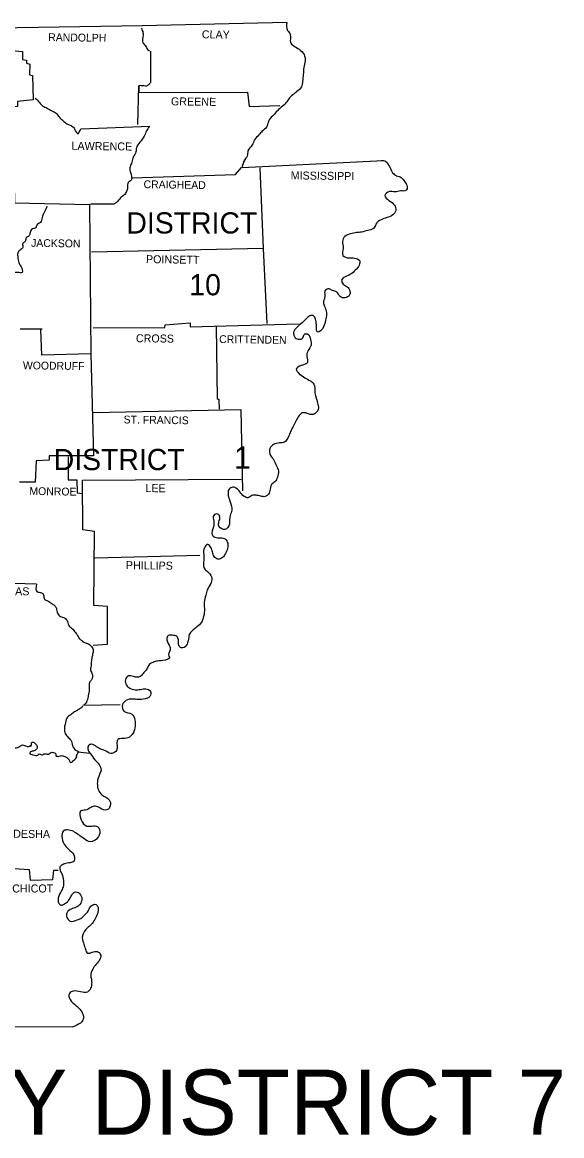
# Model space of a CAD drawing. Extents: x 185 to 5012, y 113 to 2127.
# Drawn here: x 4729 to 5012, y 1376 to 1961 of the extents above; entities that cross this region are included whole.
import ezdxf

# ---------------------------------------------------------------- set-up
doc = ezdxf.new("R2010")
doc.units = 0
for name, color, linetype in [('1', 7, 'Continuous'), ('2', 7, 'Continuous'), ('3', 7, 'Continuous')]:
    doc.layers.add(name, color=color, linetype=linetype)

msp = doc.modelspace()

# ---------------------------------------------------------------- linework, layer by layer
at = {"layer": '1'}
for p, q in [((4844.18, 1884.51), (4845.35, 1888.13)), ((4844.47, 1885.68), (4845.65, 1888.52)), ((4727.55, 1799.78), (4739.2, 1799.78)), ((4760.62, 1601.94), (4780.19, 1602.24))]:
    msp.add_line(p, q, dxfattribs=at)
for points in [[(4330.91, 1956.42), (4489.12, 1956.32), (4627.95, 1956.61), (4791.74, 1959.16), (4867.66, 1960.92)], [(4717.87, 1957.4), (4717.57, 1955.05), (4719.53, 1954.76), (4719.43, 1953.58), (4721.68, 1953.09), (4721.88, 1951.53), (4722.95, 1950.84), (4723.25, 1946.15), (4728.83, 1945.56), (4728.83, 1941.35), (4730.88, 1941.06), (4730.88, 1939.39), (4732.64, 1938.9), (4732.54, 1933.23), (4734.11, 1932.94), (4734.5, 1920.12), (4726.18, 1919.34), (4726.28, 1916.6), (4723.74, 1916.5), (4724.62, 1866.01), (4764.05, 1865.13), (4764.73, 1786.66), (4739, 1785.98), (4738.51, 1799.19)], [(4796.04, 1945.66), (4796.04, 1929.12)], [(4789.39, 1907.11), (4789.88, 1927.56), (4789.88, 1923.94), (4847.11, 1924.23), (4847.9, 1916.6), (4864.04, 1917.18)], [(4759.45, 1904.95), (4795.75, 1906.23)], [(4786.45, 1879.12), (4840.75, 1880.89), (4843.98, 1884.6)], [(4844.18, 1884.51), (4918.44, 1888.32)], [(4853.57, 1884.41), (4855.24, 1842.04), (4857.19, 1802.61)], [(4776.86, 1865.33), (4764.93, 1865.33), (4764.05, 1865.13)], [(4855.24, 1842.04), (4765.12, 1839.99)], [(4765.91, 1800.36), (4803.67, 1800.56), (4803.77, 1801.93), (4816.88, 1802.91), (4816.88, 1800.85), (4873.82, 1802.42)], [(4830.58, 1800.85), (4831.07, 1763.18), (4831.95, 1762.6), (4832.24, 1757.51)], [(4764.73, 1786.66), (4766.2, 1733.05), (4742.91, 1732.95), (4742.82, 1730.8), (4736.07, 1730.41), (4735.48, 1719.25), (4727.26, 1719.25)], [(4765.91, 1755.85), (4843.59, 1757.41)], [(4843.59, 1757.41), (4844.37, 1714.56)], [(4752.89, 1732.46), (4752.8, 1720.33), (4757.3, 1720.33), (4757.49, 1713.58), (4760.33, 1713.28)], [(4765.91, 1633.54), (4773.54, 1634.03), (4773.44, 1653.9), (4766.3, 1654.38), (4766.69, 1693.23), (4760.53, 1694.11), (4760.33, 1720.23), (4843.79, 1720.82)], [(4766.89, 1679.43), (4822.07, 1680.8)], [(4736.26, 1665.64), (4699.28, 1666.61), (4699.08, 1654.58), (4624.23, 1654.29)], [(4733.03, 1580.22), (4733.33, 1580.51), (4733.62, 1580.81), (4733.62, 1580.81)], [(4719.24, 1516.43), (4732.35, 1515.65), (4732.93, 1509.97), (4744.77, 1510.36), (4745.26, 1515.16), (4747.51, 1515.16)], [(4396.46, 1512.61), (4396.66, 1433.46), (4755.24, 1432.87)]]:
    msp.add_lwpolyline(points, dxfattribs=at)
for points in [[(4867.66, 1960.92), (4868.15, 1956.61), (4869.52, 1954.36), (4869.72, 1950.25), (4871.38, 1948.49), (4874.22, 1946.73), (4876.76, 1943.89), (4877.35, 1940.57), (4876.56, 1937.14), (4876.37, 1933.33), (4875.98, 1930), (4875.39, 1926.97), (4873.04, 1924.52), (4870.79, 1922.76), (4868.74, 1920.71), (4867.27, 1918.55), (4864.73, 1916.21), (4862.18, 1913.76), (4860.13, 1911.61), (4858.07, 1908.87), (4857.09, 1905.83), (4854.84, 1903.68), (4853.08, 1901.73), (4850.73, 1899.08), (4849.56, 1896.44), (4847.31, 1893.41), (4846.82, 1890.47), (4845.35, 1888.13), (4845.26, 1887.73)], [(4791.25, 1957.89), (4792.13, 1955.44), (4792.03, 1952.8), (4792.03, 1950.35), (4793.3, 1948.69), (4794.57, 1946.63), (4795.55, 1945.75)], [(4795.65, 1928.83), (4794.38, 1927.56), (4791.93, 1927.56), (4789.88, 1927.56)], [(4735.58, 1921), (4737.73, 1918.75), (4739.59, 1916.89), (4741.74, 1915.81), (4744.28, 1914.35), (4746.53, 1913.17), (4748, 1911.31), (4750.06, 1909.26), (4752.11, 1907.6), (4755.34, 1906.03), (4756.42, 1904.37), (4757.88, 1902.31), (4759.45, 1904.95)], [(4795.45, 1906.13), (4793.99, 1903.78), (4792.81, 1901.04), (4790.46, 1897.91), (4788.7, 1894.88), (4788.41, 1892.82), (4787.04, 1890.08), (4786.26, 1887.34), (4785.38, 1884.99), (4785.38, 1882.55), (4786.06, 1880.1), (4785.87, 1877.85), (4784.4, 1876.78), (4784.01, 1873.94), (4783.42, 1871.98), (4782.15, 1870.03), (4780.29, 1868.56), (4778.33, 1866.31), (4776.86, 1865.33)], [(4917.36, 1888.22), (4918.44, 1888.32), (4921.77, 1884.8), (4923.23, 1881.86), (4925.39, 1880.2), (4927.83, 1879.32), (4929.69, 1877.07), (4930.96, 1874.62), (4930.28, 1872.47), (4927.54, 1872.28), (4924.51, 1871.79), (4921.57, 1871.88), (4919.22, 1869.93), (4921.38, 1867.29), (4924.21, 1864.84), (4925, 1862.2), (4923.43, 1859.65), (4920.3, 1858.28), (4917.27, 1857.11), (4914.53, 1854.76), (4913.25, 1852.51), (4910.22, 1851.53), (4907.09, 1850.65), (4904.35, 1850.36), (4901.22, 1849.77), (4898.19, 1848.3), (4896.92, 1845.76), (4897.31, 1842.14), (4897.21, 1838.32), (4900.44, 1837.05), (4903.27, 1836.95), (4906.01, 1835.49), (4905.72, 1833.33), (4903.67, 1830.6), (4901.22, 1828.44), (4898.77, 1827.37), (4896.52, 1825.31), (4897.31, 1823.26), (4899.36, 1821.89), (4900.83, 1819.64), (4900.63, 1817.58), (4898.29, 1816.11), (4895.74, 1816.7), (4893.88, 1819.15), (4891.73, 1819.93), (4889.87, 1820.81), (4887.72, 1819.54), (4887.72, 1816.7), (4886.94, 1813.67), (4887.62, 1811.42), (4888.5, 1808.29), (4888.4, 1805.94), (4887.62, 1802.61), (4885.96, 1799.19), (4884, 1798.11), (4883.22, 1801.83), (4882.83, 1804.86), (4881.65, 1806.62), (4880.09, 1806.72), (4878.03, 1805.25), (4875.78, 1803), (4872.94, 1800.56), (4871.28, 1798.11), (4872.16, 1795.08), (4874.31, 1794.3), (4875.98, 1794.88), (4876.86, 1796.84), (4878.52, 1797.13), (4880.09, 1794.1)], [(4741.64, 1864.25), (4740.47, 1861.22), (4739.1, 1858.28), (4738.22, 1855.74), (4736.36, 1854.27), (4735.77, 1852.9), (4734.11, 1852.32), (4732.84, 1850.36), (4732.25, 1848.6), (4730.88, 1847.82), (4730.19, 1845.66), (4728.92, 1844.49), (4729.02, 1842.53), (4727.55, 1841.16), (4726.38, 1839.6), (4726.38, 1837.44), (4726.87, 1834.61), (4727.85, 1832.94), (4728.73, 1830.79), (4728.63, 1829.42), (4726.18, 1829.42), (4724.13, 1829.03)], [(4880.09, 1794.1), (4880.48, 1791.26), (4878.81, 1788.23), (4878.23, 1785.2), (4878.52, 1782.16), (4875.39, 1780.5), (4872.65, 1778.54), (4874.22, 1776.2), (4877.15, 1774.04), (4880.09, 1772.38), (4881.95, 1770.72), (4882.43, 1766.71), (4882.92, 1764.16), (4883.9, 1760.64), (4884.29, 1758.19), (4882.53, 1755.26), (4880.48, 1754.67), (4878.33, 1755.36), (4875.78, 1755.55), (4873.73, 1753.59), (4872.26, 1750.86), (4870.79, 1748.12), (4869.72, 1745.77), (4868.64, 1743.22), (4866.49, 1740.29), (4863.85, 1739.8), (4860.71, 1739.02), (4858.86, 1736.86), (4859.15, 1733.24), (4860.91, 1730.8), (4862.28, 1727.76), (4863.26, 1725.12), (4862.77, 1721.8), (4861.4, 1719.35), (4859.64, 1717.88), (4858.86, 1714.75), (4857.58, 1712.4), (4856.41, 1711.62), (4854.06, 1711.82), (4851.52, 1712.31), (4849.36, 1712.11), (4847.31, 1711.03), (4845.26, 1711.72), (4843.1, 1714.07), (4841.34, 1715.83), (4839.39, 1716.51), (4837.33, 1715.44), (4836.94, 1712.21), (4837.92, 1708.88), (4838.8, 1704.38), (4837.92, 1701.64), (4837.62, 1697.14)], [(4837.62, 1697.14), (4835.37, 1694.3), (4832.05, 1696.06), (4832.05, 1698.41), (4832.54, 1700.86), (4831.36, 1702.42), (4829.31, 1701.74), (4829.31, 1698.71), (4829.11, 1695.77), (4828.52, 1691.56), (4829.89, 1690.29), (4833.03, 1689.9), (4835.28, 1689.31), (4836.65, 1687.06), (4836.55, 1684.32), (4835.47, 1681.68), (4833.91, 1679.53), (4831.46, 1678.75), (4829.5, 1680.02), (4828.72, 1682.56), (4827.84, 1684.81), (4826.18, 1686.48), (4824.42, 1684.62), (4824.02, 1681.19), (4824.12, 1678.26), (4824.12, 1674.25), (4826.67, 1671.6), (4828.23, 1668.57), (4827.74, 1665.83), (4825.88, 1662.6), (4825.1, 1659.77), (4824.32, 1655.95), (4824.42, 1651.74), (4823.73, 1647.63), (4822.36, 1644.89), (4819.82, 1642.64), (4818.15, 1641.18), (4816.78, 1639.71), (4816.1, 1636.77), (4815.61, 1634.72), (4813.75, 1632.27), (4812.28, 1632.08), (4811.11, 1633.05), (4810.72, 1634.72), (4810.72, 1636.38), (4809.93, 1638.04), (4807.49, 1638.73), (4805.53, 1638.63), (4804.65, 1637.26), (4805.92, 1633.45), (4806.41, 1631), (4805.73, 1627.67), (4806.12, 1627.28), (4802.6, 1625.42), (4799.76, 1625.13), (4797.41, 1624.44), (4795.16, 1622.98), (4794.08, 1620.82), (4792.52, 1619.06), (4791.15, 1617.4), (4789.29, 1616.62), (4787.24, 1617.01), (4784.5, 1617.3), (4782.93, 1615.35), (4783.42, 1612.51), (4785.28, 1610.85), (4788.02, 1610.06), (4790.86, 1610.26), (4793.6, 1610.55), (4796.14, 1609.18), (4795.65, 1606.54), (4793.2, 1605.27), (4789.58, 1604.88), (4786.65, 1605.17), (4783.13, 1604.39), (4781.37, 1602.14), (4782.34, 1598.71), (4786.16, 1597.34), (4787.92, 1594.11), (4788.02, 1591.08), (4786.75, 1587.07), (4784.99, 1585.21), (4781.56, 1584.43), (4778.92, 1583.94), (4778.53, 1579.44), (4777.35, 1577.19), (4775.3, 1576.5), (4772.36, 1577.97), (4770.6, 1578.66), (4768.45, 1579.63), (4765.71, 1581.3), (4763.66, 1581), (4764.24, 1576.7), (4764.44, 1576.5), (4766.79, 1573.27), (4769.14, 1570.73), (4770.21, 1567.7)], [(4736.26, 1665.64), (4736.55, 1661.62), (4738.9, 1661.04), (4739.88, 1659.96), (4740.37, 1657.71), (4742.03, 1656.73), (4744.28, 1655.36), (4745.65, 1654.38), (4746.63, 1652.82), (4747.22, 1650.27), (4748.78, 1648.61), (4750.94, 1647.83), (4752.5, 1645.97), (4753.48, 1643.33), (4755.05, 1642.15), (4756.61, 1640.1), (4757.39, 1639.22), (4758.76, 1636.87), (4760.13, 1635.7), (4761.11, 1635.01), (4762.68, 1634.52), (4764.63, 1633.25), (4765.91, 1631.29), (4765.91, 1629.83), (4765.42, 1627.58), (4765.03, 1625.23), (4764.83, 1622.59), (4764.63, 1620.24), (4765.52, 1618.28), (4765.03, 1615.35), (4764.05, 1613.78), (4763.95, 1611.63), (4763.66, 1608.4), (4763.26, 1606.54), (4762.38, 1603.51), (4761.11, 1601.94)], [(4699.08, 1615.05), (4700.55, 1614.07), (4702.6, 1614.17), (4703.97, 1614.76), (4705.05, 1614.66), (4706.52, 1613.78), (4707.5, 1612.61), (4708.18, 1611.73), (4708.67, 1610.36), (4708.67, 1609.08), (4709.16, 1607.32), (4709.75, 1606.64), (4710.53, 1605.37), (4711.02, 1604.19), (4711.31, 1603.41), (4712.39, 1602.14), (4713.37, 1602.24), (4714.25, 1602.14), (4715.42, 1601.45), (4717.18, 1600.08), (4717.48, 1599.69), (4718.65, 1597.15), (4718.85, 1595.58), (4719.04, 1593.53), (4719.43, 1591.57), (4720.22, 1589.42), (4720.61, 1587.95), (4721.49, 1585.9), (4722.07, 1584.53), (4722.86, 1582.76), (4724.03, 1580.81), (4724.52, 1579.63), (4726.18, 1579.73), (4727.36, 1580.22), (4728.24, 1581), (4729.31, 1580.91), (4730.49, 1580.51), (4732.05, 1580.22), (4733.03, 1580.81), (4733.52, 1581.2), (4733.62, 1582.08), (4734.5, 1582.57), (4735.48, 1581.88), (4736.55, 1580.32), (4736.55, 1579.34), (4736.16, 1578.75), (4734.89, 1577.97), (4733.13, 1577.38), (4732.64, 1576.7), (4734.3, 1575.92), (4736.95, 1575.72), (4737.63, 1576.31), (4739.39, 1575.82), (4740.08, 1576.31), (4742.42, 1576.21), (4743.5, 1576.99), (4745.65, 1576.89), (4746.34, 1576.41), (4746.34, 1575.52), (4748.1, 1575.13), (4749.37, 1575.43), (4751.03, 1574.94), (4752.5, 1574.15), (4753.29, 1573.08), (4754.26, 1571.9), (4755.14, 1572.2), (4755.83, 1573.08), (4757.3, 1574.64), (4757.3, 1575.62), (4757.69, 1576.31), (4758.18, 1577.29)], [(4760.43, 1601.35), (4758.37, 1599.69), (4756.61, 1598.71), (4754.75, 1597.34), (4752.5, 1595.68), (4751.43, 1592.84), (4750.84, 1588.93), (4751.62, 1586.58), (4753.38, 1584.53), (4754.56, 1582.86), (4755.44, 1579.93), (4757.59, 1577.87), (4758.28, 1577.58)], [(4770.21, 1567.7), (4769.23, 1565.45), (4768.16, 1561.53), (4768.45, 1558.21), (4769.92, 1555.37), (4772.27, 1553.8), (4774.81, 1551.55), (4774.61, 1548.13), (4773.15, 1546.86), (4769.72, 1547.74), (4767.08, 1548.91), (4764.83, 1548.23), (4761.8, 1546.76), (4759.55, 1546.47), (4759.64, 1541.77), (4762.68, 1538.44), (4765.32, 1538.44), (4768.35, 1538.05), (4769.43, 1534.53), (4767.67, 1531.59), (4764.73, 1530.13), (4761.01, 1531.89), (4758.37, 1533.75), (4755.73, 1535.51), (4752.4, 1536.39), (4750.55, 1536), (4749.67, 1531.89), (4751.23, 1528.17), (4753.77, 1525.63), (4756.12, 1522.3), (4755.73, 1519.85), (4753.97, 1519.17), (4750.84, 1518.48), (4748.98, 1517.51), (4748.49, 1516.72), (4749.47, 1513.4), (4750.35, 1509.78), (4750.35, 1507.04), (4749.27, 1504.49), (4747.61, 1500.58), (4747.81, 1498.03), (4748.98, 1496.86), (4750.45, 1497.25), (4752.4, 1498.62), (4753.68, 1500.19), (4754.75, 1502.14), (4756.81, 1503.81), (4759.35, 1502.34), (4759.94, 1499.31), (4758.47, 1496.67), (4756.42, 1495.49), (4753.87, 1494.51), (4752.01, 1492.36), (4752.5, 1489.82), (4753.97, 1488.45), (4757.59, 1489.13), (4760.04, 1490.21), (4761.41, 1491.58), (4763.07, 1493.24), (4763.95, 1494.9), (4765.22, 1496.67), (4767.47, 1497.15), (4768.55, 1495.69), (4768.16, 1492.36), (4766.79, 1489.23), (4764.93, 1486.59), (4762.87, 1484.73), (4760.33, 1480.72), (4760.82, 1477), (4761.8, 1473.97), (4763.17, 1471.62), (4765.52, 1472.11), (4768.16, 1472.4), (4769.72, 1471.13), (4769.53, 1468.39), (4767.57, 1465.75), (4765.71, 1463.2), (4764.73, 1459.68), (4765.12, 1457.24), (4765.12, 1454.98), (4764.34, 1452.54), (4762.97, 1451.17), (4759.35, 1451.27), (4755.54, 1451.66), (4753.48, 1450.48), (4753.87, 1447.16), (4756.12, 1444.71), (4757.69, 1443.44), (4759.94, 1440.7), (4760.92, 1438.45), (4760.62, 1436.49), (4759.25, 1434.83), (4755.24, 1432.87)]]:
    msp.add_spline(points, degree=3, dxfattribs=at)
at = {"layer": '3'}
msp.add_line((4757.98, 1577.48), (4764.15, 1576.7), dxfattribs=at)

# ---------------------------------------------------------------- texts
at = {"layer": '1'}
msp.add_text('1', height=11.74, dxfattribs=at).set_placement((4839.97, 1726.2))
at = {"layer": '2'}
for s, height, rotation, p in [('RANDOLPH', 4.109, 359.25835, (4742.33, 1951.04)), ('CLAY', 4.206, 359.22578, (4823.05, 1952.5)), ('GREENE', 4.207, 359.2361, (4806.8, 1917.28)), ('LAWRENCE', 4.207, 359.26783, (4754.56, 1893.9)), ('MISSISSIPPI', 4.2062, 359.30972, (4869.72, 1878.34)), ('CRAIGHEAD', 4.109, 359.11587, (4792.42, 1873.74)), ('JACKSON', 4.108, 359.13523, (4733.33, 1842.92)), ('POINSETT', 4.206, 359.19871, (4793.69, 1834.31)), ('CROSS', 4.206, 359.38394, (4788.41, 1792.73)), ('CRITTENDEN', 4.109, 359.21302, (4832.14, 1792.34)), ('WOODRUFF', 4.108, 359.27478, (4729.02, 1778.54)), ('ST. FRANCIS', 4.1081, 359.22157, (4781.95, 1750.07)), ('MONROE', 4.108, 359.03308, (4732.45, 1712.5)), ('LEE', 4.207, 359.43273, (4793.4, 1713.97)), ('PHILLIPS', 4.206, 359.31794, (4783.13, 1673.46)), ('ARKANSAS', 4.206, 359.26783, (4701.82, 1660.06)), ('DESHA', 4.206, 359.3704, (4723.93, 1532.28))]:
    msp.add_text(s, height=height, rotation=rotation, dxfattribs=at).set_placement(p)
for s, height, p in [('CHICOT', 4.207, (4723.44, 1503.51)), ('ARKANSAS HIGHWAY DISTRICT 7', 34.244, (4271.47, 1376.13))]:
    msp.add_text(s, height=height, dxfattribs=at).set_placement(p)
at = {"layer": '3'}
for s, p in [('DISTRICT', (4783.42, 1849.87)), ('10', (4816.49, 1817.39)), ('DISTRICT', (4745.26, 1725.51))]:
    msp.add_text(s, height=11.154, dxfattribs=at).set_placement(p)

doc.saveas('drawing.dxf')
